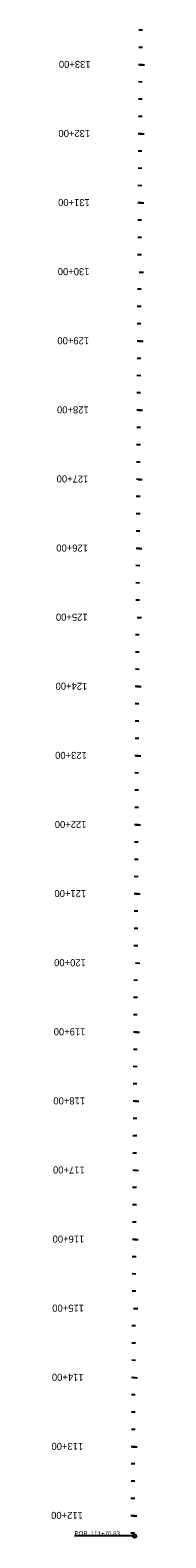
# Model space of a CAD drawing. Extents: x 17535628 to 17537899, y 7333852 to 7342653.
# Drawn here: x 17535628 to 17535763, y 7333852 to 7336033 of the extents above; entities that cross this region are included whole.
import ezdxf

# ---------------------------------------------------------------- set-up
doc = ezdxf.new("R2010")
doc.units = 0
for name, color, linetype in [('TextAlignment', 7, 'Continuous'), ('TextAlignmentLrg', 7, 'Continuous'), ('TextAlignmentSml', 7, 'Continuous')]:
    doc.layers.add(name, color=color, linetype=linetype)

msp = doc.modelspace()

# ---------------------------------------------------------------- linework, layer by layer
at = {"layer": 'TextAlignment'}
msp.add_line((17535748.4, 7333854.2), (17535661.4, 7333854.6), dxfattribs=at)
msp.add_circle((17535748.4, 7333854.2), 2.67, dxfattribs=at)
at = {"layer": 'TextAlignmentLrg'}
for p, q in [((17535759.7, 7335983.3), (17535754.3, 7335983.4)), ((17535759.2, 7335883.3), (17535753.7, 7335883.4)), ((17535758.7, 7335783.3), (17535753.2, 7335783.4)), ((17535755.1, 7335683.3), (17535761.2, 7335683.3)), ((17535757.6, 7335583.3), (17535752.1, 7335583.4)), ((17535757.1, 7335483.3), (17535751.6, 7335483.4)), ((17535756.5, 7335383.3), (17535751.1, 7335383.4)), ((17535756, 7335283.3), (17535750.5, 7335283.4)), ((17535752.4, 7335183.4), (17535758.5, 7335183.3)), ((17535754.9, 7335083.3), (17535749.5, 7335083.4)), ((17535754.4, 7334983.3), (17535749, 7334983.4)), ((17535753.9, 7334883.3), (17535748.4, 7334883.4)), ((17535753.4, 7334783.3), (17535747.9, 7334783.4)), ((17535749.8, 7334683.4), (17535755.9, 7334683.3)), ((17535752.3, 7334583.3), (17535746.8, 7334583.4)), ((17535751.8, 7334483.3), (17535746.3, 7334483.4)), ((17535751.2, 7334383.3), (17535745.8, 7334383.4)), ((17535750.7, 7334283.3), (17535745.2, 7334283.4)), ((17535747.1, 7334183.4), (17535753.2, 7334183.3)), ((17535749.6, 7334083.3), (17535744.2, 7334083.4)), ((17535749.1, 7333983.4), (17535743.6, 7333983.4)), ((17535748.6, 7333883.4), (17535743.1, 7333883.4))]:
    msp.add_line(p, q, dxfattribs=at)
at = {"layer": 'TextAlignmentSml'}
for p, q in [((17535760, 7336033.3), (17535754.5, 7336033.4)), ((17535759.9, 7336008.3), (17535754.4, 7336008.4)), ((17535756.7, 7335983.3), (17535762.8, 7335983.3)), ((17535759.6, 7335958.3), (17535754.1, 7335958.4)), ((17535759.5, 7335933.3), (17535754, 7335933.4)), ((17535759.3, 7335908.3), (17535753.9, 7335908.4)), ((17535756.1, 7335883.3), (17535762.3, 7335883.3)), ((17535759.1, 7335858.3), (17535753.6, 7335858.4)), ((17535758.9, 7335833.3), (17535753.5, 7335833.4)), ((17535758.8, 7335808.3), (17535753.3, 7335808.4)), ((17535755.6, 7335783.3), (17535761.7, 7335783.3)), ((17535758.5, 7335758.3), (17535753.1, 7335758.4)), ((17535758.4, 7335733.3), (17535752.9, 7335733.4)), ((17535758.3, 7335708.3), (17535752.8, 7335708.4)), ((17535755.1, 7335683.3), (17535761.2, 7335683.3)), ((17535758, 7335658.3), (17535752.5, 7335658.4)), ((17535757.9, 7335633.3), (17535752.4, 7335633.4)), ((17535757.7, 7335608.3), (17535752.3, 7335608.4)), ((17535754.5, 7335583.3), (17535760.7, 7335583.3)), ((17535757.5, 7335558.3), (17535752, 7335558.4)), ((17535757.3, 7335533.3), (17535751.9, 7335533.4)), ((17535757.2, 7335508.3), (17535751.7, 7335508.4)), ((17535754, 7335483.3), (17535760.1, 7335483.3)), ((17535756.9, 7335458.3), (17535751.5, 7335458.4)), ((17535756.8, 7335433.3), (17535751.3, 7335433.4)), ((17535756.7, 7335408.3), (17535751.2, 7335408.4)), ((17535753.5, 7335383.3), (17535759.6, 7335383.3)), ((17535756.4, 7335358.3), (17535750.9, 7335358.4)), ((17535756.3, 7335333.3), (17535750.8, 7335333.4)), ((17535756.1, 7335308.3), (17535750.7, 7335308.4)), ((17535752.9, 7335283.3), (17535759.1, 7335283.3)), ((17535755.9, 7335258.3), (17535750.4, 7335258.4)), ((17535755.7, 7335233.3), (17535750.3, 7335233.4)), ((17535755.6, 7335208.3), (17535750.2, 7335208.4)), ((17535752.4, 7335183.4), (17535758.5, 7335183.3)), ((17535755.3, 7335158.3), (17535749.9, 7335158.4)), ((17535755.2, 7335133.3), (17535749.8, 7335133.4)), ((17535755.1, 7335108.3), (17535749.6, 7335108.4)), ((17535751.9, 7335083.4), (17535758, 7335083.3)), ((17535754.8, 7335058.3), (17535749.4, 7335058.4)), ((17535754.7, 7335033.3), (17535749.2, 7335033.4)), ((17535754.5, 7335008.3), (17535749.1, 7335008.4)), ((17535751.4, 7334983.4), (17535757.5, 7334983.3)), ((17535754.3, 7334958.3), (17535748.8, 7334958.4)), ((17535754.2, 7334933.3), (17535748.7, 7334933.4)), ((17535754, 7334908.3), (17535748.6, 7334908.4)), ((17535750.8, 7334883.4), (17535756.9, 7334883.3)), ((17535753.8, 7334858.3), (17535748.3, 7334858.4)), ((17535753.6, 7334833.3), (17535748.2, 7334833.4)), ((17535753.5, 7334808.3), (17535748, 7334808.4)), ((17535750.3, 7334783.4), (17535756.4, 7334783.3)), ((17535753.2, 7334758.3), (17535747.8, 7334758.4)), ((17535753.1, 7334733.3), (17535747.6, 7334733.4)), ((17535753, 7334708.3), (17535747.5, 7334708.4)), ((17535749.8, 7334683.4), (17535755.9, 7334683.3)), ((17535752.7, 7334658.3), (17535747.2, 7334658.4)), ((17535752.6, 7334633.3), (17535747.1, 7334633.4)), ((17535752.4, 7334608.3), (17535747, 7334608.4)), ((17535749.2, 7334583.4), (17535755.4, 7334583.3)), ((17535752.2, 7334558.3), (17535746.7, 7334558.4)), ((17535752, 7334533.3), (17535746.6, 7334533.4)), ((17535751.9, 7334508.3), (17535746.4, 7334508.4)), ((17535748.7, 7334483.4), (17535754.8, 7334483.3)), ((17535751.6, 7334458.3), (17535746.2, 7334458.4)), ((17535751.5, 7334433.3), (17535746, 7334433.4)), ((17535751.4, 7334408.3), (17535745.9, 7334408.4)), ((17535748.2, 7334383.4), (17535754.3, 7334383.3)), ((17535751.1, 7334358.3), (17535745.6, 7334358.4)), ((17535751, 7334333.3), (17535745.5, 7334333.4)), ((17535750.8, 7334308.3), (17535745.4, 7334308.4)), ((17535747.6, 7334283.4), (17535753.8, 7334283.3)), ((17535750.6, 7334258.3), (17535745.1, 7334258.4)), ((17535750.4, 7334233.3), (17535745, 7334233.4)), ((17535750.3, 7334208.3), (17535744.8, 7334208.4)), ((17535747.1, 7334183.4), (17535753.2, 7334183.3)), ((17535750, 7334158.3), (17535744.6, 7334158.4)), ((17535749.9, 7334133.3), (17535744.4, 7334133.4)), ((17535749.8, 7334108.3), (17535744.3, 7334108.4)), ((17535746.6, 7334083.4), (17535752.7, 7334083.3)), ((17535749.5, 7334058.4), (17535744, 7334058.4)), ((17535749.4, 7334033.4), (17535743.9, 7334033.4)), ((17535749.2, 7334008.4), (17535743.8, 7334008.4)), ((17535746, 7333983.4), (17535752.2, 7333983.3)), ((17535749, 7333958.4), (17535743.5, 7333958.4)), ((17535748.8, 7333933.4), (17535743.4, 7333933.4)), ((17535748.7, 7333908.4), (17535743.2, 7333908.4)), ((17535745.5, 7333883.4), (17535751.6, 7333883.3)), ((17535748.4, 7333858.4), (17535743, 7333858.4))]:
    msp.add_line(p, q, dxfattribs=at)

# ---------------------------------------------------------------- texts
at = {"layer": 'TextAlignment'}
for s, p in [('POB ', (17535661.4, 7333854.8)), ('111+70.83', (17535684.8, 7333854.6))]:
    msp.add_text(s, height=6.48, rotation=359.6959, dxfattribs=at).set_placement(p)
at = {"layer": 'TextAlignmentLrg'}
for s, p in [('130+00', (17535683.2, 7335688.8)), ('125+00', (17535680.5, 7335188.8)), ('120+00', (17535677.9, 7334688.8)), ('115+00', (17535675.2, 7334188.8))]:
    msp.add_text(s, height=10.2, rotation=179.6959, dxfattribs=at).set_placement(p)
at = {"layer": 'TextAlignmentSml'}
for s, p in [('133+00', (17535684.8, 7335988.8)), ('132+00', (17535684.2, 7335888.8)), ('131+00', (17535683.7, 7335788.8)), ('130+00', (17535683.2, 7335688.8)), ('129+00', (17535682.6, 7335588.8)), ('128+00', (17535682.1, 7335488.8)), ('127+00', (17535681.6, 7335388.8)), ('126+00', (17535681, 7335288.8)), ('125+00', (17535680.5, 7335188.8)), ('124+00', (17535680, 7335088.8)), ('123+00', (17535679.4, 7334988.8)), ('122+00', (17535678.9, 7334888.8)), ('121+00', (17535678.4, 7334788.8)), ('120+00', (17535677.9, 7334688.8)), ('119+00', (17535677.3, 7334588.8)), ('118+00', (17535676.8, 7334488.8)), ('117+00', (17535676.3, 7334388.8)), ('116+00', (17535675.7, 7334288.8)), ('115+00', (17535675.2, 7334188.8)), ('114+00', (17535674.7, 7334088.8)), ('113+00', (17535674.1, 7333988.8)), ('112+00', (17535673.6, 7333888.9))]:
    msp.add_text(s, height=10.2, rotation=179.6959, dxfattribs=at).set_placement(p)

doc.saveas('drawing.dxf')
